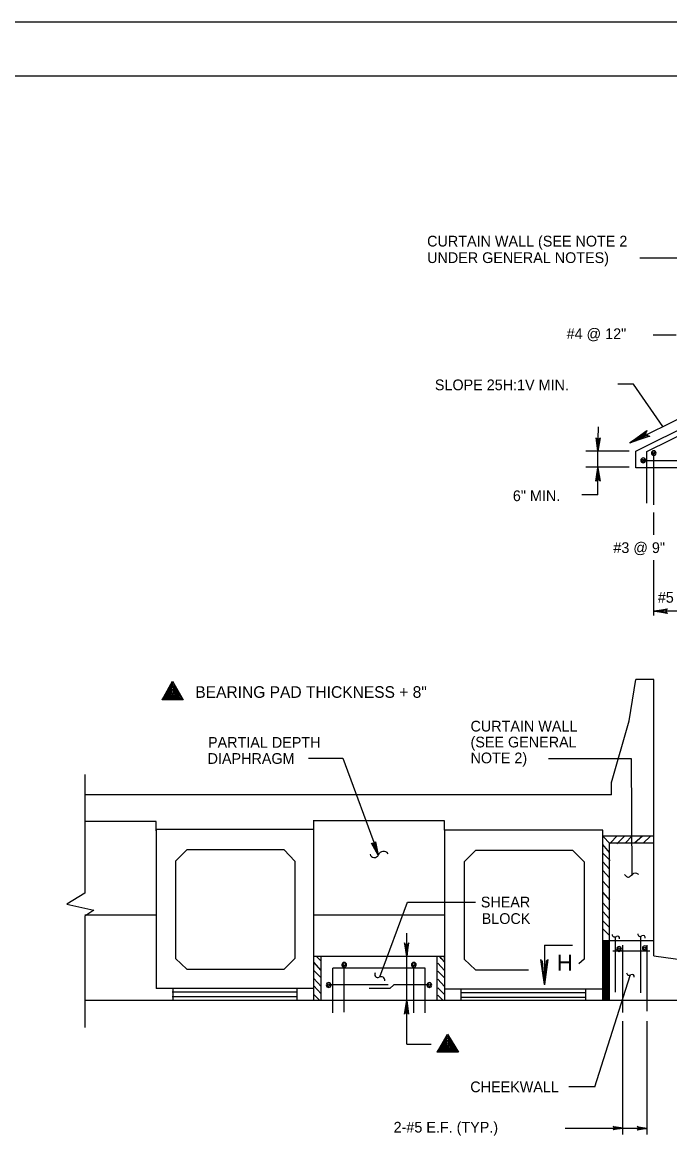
# Model space of a CAD drawing. Extents: x 638091 to 638946, y 298288 to 298882.
# Drawn here: x 638535 to 638715.9, y 298569.7 to 298881.5 of the extents above; entities that cross this region are included whole.
import ezdxf

# ---------------------------------------------------------------- set-up
doc = ezdxf.new("R2010")
doc.units = 0
doc.layers.add('2', color=7, linetype='Continuous')
doc.layers.add('PLT-BNDY', color=7, linetype='Continuous')

msp = doc.modelspace()

# ---------------------------------------------------------------- linework, layer by layer
at = {"layer": '2'}
for p, q in [((638130.58, 298866.5), (638916.58, 298866.5)), ((638707.59, 298815.66), (638719.77, 298815.66)), ((638717.8, 298794.07), (638711.37, 298794.07)), ((638705.85, 298780.38), (638701.42, 298780.38)), ((638714.07, 298768.52), (638705.85, 298780.38)), ((638704.85, 298763.94), (638721.09, 298772)), ((638695.91, 298761.63), (638696.1, 298768.38)), ((638706.51, 298761.63), (638722.75, 298769.7)), ((638709.54, 298761.48), (638723.83, 298768.57)), ((638704.66, 298761.63), (638692.53, 298761.63)), ((638695.91, 298756.95), (638695.91, 298761.63)), ((638706.51, 298756.95), (638706.51, 298761.63)), ((638708.54, 298759.05), (638728.54, 298759.05)), ((638708.54, 298758.38), (638708.54, 298758.73)), ((638709.54, 298747.04), (638709.54, 298761.48)), ((638711.5, 298746.64), (638711.5, 298761.08)), ((638711.5, 298760.41), (638711.5, 298760.77)), ((638704.66, 298757.13), (638692.53, 298757.13)), ((638695.91, 298749.38), (638695.91, 298756.95)), ((638872.72, 298756.95), (638706.51, 298756.95)), ((638695.91, 298749.38), (638691.41, 298749.38)), ((638711.5, 298738.24), (638711.5, 298744.51)), ((638711.5, 298715.67), (638711.5, 298731.15)), ((638813.89, 298716.87), (638711.5, 298716.87)), ((638704.6, 298686.2), (638706.47, 298697.82)), ((638711.53, 298697.82), (638706.47, 298697.82)), ((638711.53, 298653.95), (638711.53, 298697.82)), ((638699.72, 298668.95), (638704.6, 298686.2)), ((638614.96, 298675.78), (638624.6, 298675.78)), ((638624.6, 298675.78), (638634.56, 298648.73)), ((638682.1, 298675.7), (638705.16, 298675.7)), ((638705.16, 298675.7), (638705.35, 298643.07)), ((638552.53, 298671.2), (638552.53, 298638.01)), ((638699.72, 298665.57), (638699.72, 298669.14)), ((638699.72, 298665.57), (638552.53, 298665.57)), ((638572.41, 298658.07), (638552.53, 298658.07)), ((638572.41, 298655.45), (638572.41, 298658.07)), ((638572.41, 298655.82), (638572.41, 298611.39)), ((638616.47, 298655.82), (638572.41, 298655.82)), ((638616.47, 298655.82), (638616.47, 298658.45)), ((638653.03, 298658.26), (638616.47, 298658.26)), ((638616.47, 298608.01), (638616.47, 298655.82)), ((638653.03, 298655.64), (638653.03, 298658.26)), ((638653.03, 298655.64), (638653.03, 298608.01)), ((638697.28, 298655.64), (638653.03, 298655.64)), ((638697.28, 298608.01), (638697.28, 298655.64)), ((638697.28, 298653.95), (638699.35, 298651.89)), ((638711.53, 298653.95), (638697.28, 298653.95)), ((638701.22, 298653.95), (638699.53, 298652.26)), ((638703.28, 298653.95), (638701.22, 298651.89)), ((638705.53, 298654.14), (638703.47, 298652.07)), ((638708.35, 298653.95), (638706.1, 298652.07)), ((638710.6, 298653.95), (638708.53, 298652.07)), ((638711.53, 298620.57), (638711.53, 298653.95)), ((638577.85, 298647.01), (638581.03, 298650.2)), ((638608.22, 298650.2), (638581.03, 298650.2)), ((638608.22, 298650.2), (638611.22, 298647.01)), ((638658.47, 298646.82), (638661.66, 298650.01)), ((638688.85, 298650.01), (638661.66, 298650.01)), ((638688.85, 298650.01), (638692.03, 298646.82)), ((638699.16, 298649.45), (638697.28, 298651.7)), ((638699.16, 298608.01), (638699.16, 298652.07)), ((638711.53, 298652.07), (638699.16, 298652.07)), ((638577.85, 298647.01), (638577.85, 298619.82)), ((638611.22, 298647.01), (638611.22, 298619.82)), ((638658.47, 298646.82), (638658.47, 298619.64)), ((638692.03, 298646.82), (638692.03, 298619.64)), ((638697.28, 298649.26), (638699.35, 298647.2)), ((638699.16, 298644.76), (638697.28, 298646.82)), ((638699.16, 298642.32), (638697.28, 298644.39)), ((638699.16, 298639.32), (638697.28, 298641.39)), ((638697.28, 298638.2), (638699.16, 298636.14)), ((638634.96, 298614.65), (638642.72, 298635.57)), ((638642.72, 298635.57), (638661.66, 298635.57)), ((638699.16, 298633.32), (638697.28, 298635.39)), ((638572.41, 298631.89), (638552.53, 298631.89)), ((638552.53, 298631.64), (638552.53, 298600.51)), ((638653.03, 298631.89), (638616.47, 298631.89)), ((638699.16, 298630.89), (638697.28, 298632.95)), ((638699.16, 298628.45), (638697.28, 298630.32)), ((638699.16, 298626.2), (638697.28, 298628.07)), ((638642.46, 298595.82), (638642.46, 298626.86)), ((638699.16, 298624.7), (638697.28, 298624.7)), ((638697.47, 298608.01), (638697.47, 298624.7)), ((638697.85, 298608.01), (638697.85, 298624.7)), ((638698.22, 298608.01), (638698.22, 298624.7)), ((638698.6, 298608.01), (638698.6, 298624.7)), ((638698.97, 298608.01), (638698.97, 298624.7)), ((638711.53, 298624.7), (638699.16, 298624.7)), ((638700.83, 298610.36), (638700.83, 298625.73)), ((638707.89, 298610.17), (638707.89, 298625.92)), ((638680.92, 298623.53), (638680.92, 298612.4)), ((638680.92, 298623.53), (638688.75, 298623.53)), ((638710.4, 298621.8), (638700.09, 298621.8)), ((638701.79, 298621.77), (638701.79, 298622.12)), ((638702.87, 298604.73), (638702.87, 298623.51)), ((638708.97, 298621.99), (638708.97, 298622.35)), ((638709.61, 298605.11), (638709.61, 298623.51)), ((638581.03, 298616.82), (638577.85, 298619.82)), ((638611.22, 298619.82), (638608.22, 298616.82)), ((638653.03, 298620.39), (638616.47, 298620.39)), ((638618.53, 298616.45), (638616.47, 298618.72)), ((638618.53, 298619.07), (638617.22, 298620.39)), ((638618.53, 298608.01), (638618.53, 298620.39)), ((638650.97, 298608.01), (638650.97, 298620.39)), ((638653.03, 298616.45), (638651.16, 298618.51)), ((638653.03, 298618.89), (638651.72, 298620.39)), ((638652.1, 298619.82), (638651.72, 298620.39)), ((638653.03, 298619.82), (638653.03, 298620.39)), ((638661.66, 298616.64), (638658.47, 298619.64)), ((638692.03, 298619.64), (638690.57, 298618.26)), ((638711.53, 298620.57), (638754.44, 298614.58)), ((638581.03, 298616.82), (638608.22, 298616.82)), ((638618.53, 298614.39), (638616.47, 298616.45)), ((638621.8, 298604.64), (638621.8, 298617.09)), ((638647.62, 298617.09), (638621.8, 298617.09)), ((638624.95, 298604.82), (638624.95, 298617.19)), ((638624.98, 298617.37), (638624.98, 298617.73)), ((638644.43, 298617.36), (638644.43, 298617.72)), ((638644.47, 298604.64), (638644.47, 298617.01)), ((638647.62, 298604.64), (638647.62, 298617.09)), ((638653.03, 298614.39), (638651.16, 298616.26)), ((638661.66, 298616.64), (638676.52, 298616.64)), ((638695.05, 298583.87), (638704.9, 298615.08)), ((638618.53, 298611.95), (638616.47, 298614.22)), ((638618.53, 298609.87), (638616.47, 298612.16)), ((638620.64, 298611.7), (638620.64, 298612.06)), ((638637.23, 298612.47), (638620.67, 298612.47)), ((638637.78, 298611.41), (638638.85, 298612.47)), ((638648.35, 298612.47), (638638.85, 298612.47)), ((638648.79, 298611.71), (638648.79, 298612.07)), ((638653.03, 298611.95), (638651.16, 298614.01)), ((638616.47, 298611.39), (638572.41, 298611.39)), ((638576.91, 298610.45), (638611.78, 298610.45)), ((638576.91, 298609.14), (638611.78, 298609.14)), ((638577.1, 298611.2), (638577.1, 298608.01)), ((638611.78, 298611.39), (638611.78, 298608.01)), ((638618.16, 298608.01), (638616.47, 298609.7)), ((638637.78, 298611.41), (638631.92, 298611.41)), ((638653.03, 298609.7), (638651.16, 298611.57)), ((638652.66, 298608.01), (638651.16, 298609.51)), ((638697.28, 298611.2), (638653.03, 298611.2)), ((638657.53, 298608.95), (638692.41, 298608.95)), ((638657.6, 298611.21), (638657.6, 298608.02)), ((638657.72, 298610.26), (638692.41, 298610.26)), ((638692.41, 298611.21), (638692.41, 298608.02)), ((638754.44, 298608.01), (638552.53, 298608.01)), ((638702.87, 298570.62), (638702.87, 298602.23)), ((638709.61, 298570.62), (638709.61, 298602.23)), ((638642.46, 298595.82), (638649.3, 298595.82)), ((638695.05, 298583.87), (638687.76, 298583.87)), ((638709.61, 298572.31), (638686.74, 298572.31))]:
    msp.add_line(p, q, dxfattribs=at)
for points in [[(638696.41, 298765.13), (638696.16, 298765.01), (638695.91, 298761.63), (638696.41, 298765.13), (638696.53, 298765.38), (638695.91, 298761.63), (638695.78, 298765.01), (638695.53, 298765.13), (638695.91, 298761.63), (638695.41, 298765.38), (638695.53, 298765.13)], [(638710.06, 298765.82), (638709.71, 298766.06), (638704.85, 298763.94), (638710.06, 298765.82), (638710.43, 298765.77), (638704.85, 298763.94), (638709.42, 298766.68), (638709.48, 298767.05), (638704.85, 298763.94), (638709.53, 298767.42), (638709.48, 298767.05)], [(638695.53, 298753.45), (638695.78, 298753.57), (638695.91, 298756.95), (638695.53, 298753.45), (638695.28, 298753.2), (638695.91, 298756.95), (638696.16, 298753.57), (638696.41, 298753.45), (638695.91, 298756.95), (638696.53, 298753.2), (638696.41, 298753.45)], [(638715.13, 298716.5), (638715, 298716.75), (638711.5, 298716.87), (638715.13, 298716.5), (638715.25, 298716.25), (638711.5, 298716.87), (638715, 298717.12), (638715.13, 298717.37), (638711.5, 298716.87), (638715.25, 298717.5), (638715.13, 298717.37)], [(638574.08, 298692.13), (638576.96, 298697.35), (638580.02, 298692.13), (638574.08, 298692.13), (638577.14, 298696.99), (638579.66, 298692.31), (638574.26, 298692.31), (638577.14, 298696.45), (638579.48, 298692.49), (638574.62, 298692.49), (638577.14, 298696.09), (638578.94, 298692.67), (638575.16, 298692.67), (638576.96, 298695.73), (638578.58, 298692.85), (638575.52, 298692.85), (638576.96, 298695.19), (638578.22, 298693.03), (638575.88, 298693.03), (638576.96, 298694.83), (638577.86, 298693.21), (638576.24, 298693.21), (638576.96, 298694.29), (638577.32, 298693.57), (638576.78, 298693.57), (638576.96, 298693.75)], [(638633.6, 298652.32), (638633.47, 298652.07), (638634.47, 298648.7), (638633.6, 298652.32), (638633.72, 298652.45), (638634.47, 298648.7), (638633.09, 298651.95), (638632.84, 298651.95), (638634.47, 298648.7), (638632.59, 298652.07), (638632.84, 298651.95)], [(638552.53, 298638.01), (638547.47, 298635.01), (638554.97, 298633.32), (638552.53, 298631.64)], [(638641.96, 298623.89), (638642.21, 298623.76), (638642.46, 298620.39), (638641.96, 298623.89), (638641.84, 298624.14), (638642.46, 298620.39), (638642.59, 298623.76), (638642.84, 298623.89), (638642.46, 298620.39), (638643.09, 298624.14), (638642.84, 298623.89)], [(638681.92, 298619.28), (638681.42, 298619.03), (638680.92, 298612.53), (638681.92, 298619.28), (638681.92, 298619.53), (638680.92, 298612.53), (638680.42, 298619.03), (638679.92, 298619.03), (638680.92, 298612.53), (638679.92, 298619.53), (638679.92, 298619.03)], [(638641.96, 298604.51), (638642.21, 298604.64), (638642.46, 298608.01), (638641.96, 298604.51), (638641.84, 298604.26), (638642.46, 298608.01), (638642.59, 298604.64), (638642.84, 298604.51), (638642.46, 298608.01), (638642.96, 298604.26), (638642.84, 298604.51)], [(638651, 298593.63), (638653.88, 298598.67), (638656.94, 298593.63), (638651, 298593.63), (638653.88, 298598.31), (638656.58, 298593.81), (638651.18, 298593.81), (638653.88, 298597.95), (638656.4, 298593.99), (638651.54, 298593.99), (638653.88, 298597.59), (638655.86, 298594.17), (638651.9, 298594.17), (638653.88, 298597.05), (638655.5, 298594.35), (638652.26, 298594.35), (638653.88, 298596.69), (638655.14, 298594.53), (638652.8, 298594.53), (638653.88, 298596.15), (638654.78, 298594.71), (638653.16, 298594.71), (638653.88, 298595.61), (638654.24, 298595.07), (638653.7, 298595.07), (638653.88, 298595.25)], [(638700.3, 298572.72), (638700.43, 298572.47), (638702.93, 298572.35), (638700.3, 298572.72), (638700.18, 298572.85), (638702.93, 298572.35), (638700.43, 298572.22), (638700.3, 298572.1), (638702.93, 298572.35), (638700.18, 298571.85), (638700.3, 298572.1)], [(638707.11, 298572.68), (638707.11, 298572.43), (638709.61, 298572.31), (638707.11, 298572.68), (638706.86, 298572.81), (638709.61, 298572.31), (638707.11, 298572.18), (638707.11, 298572.06), (638709.61, 298572.31), (638706.86, 298571.81), (638707.11, 298572.06)]]:
    msp.add_lwpolyline(points, dxfattribs=at)
for centre in [(638708.54, 298759.05), (638711.5, 298761.08), (638701.79, 298622.44), (638708.98, 298622.66), (638624.99, 298618.04), (638644.43, 298618.04), (638620.64, 298612.37), (638648.79, 298612.38)]:
    msp.add_circle(centre, 0.314, dxfattribs=at)
for centre, radius, start, end in [((638711.5, 298761.08), 0.671, 269.6129, 268.6063), ((638708.54, 298759.05), 0.671, 271.3937, 270.3871), ((638636, 298648.21), 1.53, 35.4213, 160.213), ((638633.43, 298649.27), 1.25, 193.8117, 334.5116), ((638700.6, 298626.55), 0.738, 183.3846, 308.1762), ((638701.38, 298625.46), 0.601, 341.7749, 122.4748), ((638707.74, 298626.71), 0.738, 183.3846, 308.1762), ((638708.52, 298625.62), 0.601, 341.7749, 122.4748), ((638701.79, 298622.44), 0.671, 269.6129, 268.6063), ((638708.98, 298622.66), 0.671, 269.6129, 268.6063), ((638624.99, 298618.04), 0.671, 269.6129, 268.6063), ((638644.43, 298618.04), 0.671, 269.6129, 268.6063), ((638634.39, 298615.39), 0.89, 153.2611, 293.961), ((638704.65, 298615.83), 0.738, 183.3846, 308.1762), ((638705.42, 298614.75), 0.601, 341.7749, 122.4748), ((638620.64, 298612.37), 0.671, 269.6129, 268.6063), ((638635.29, 298613.62), 1.09, 354.8707, 119.6623), ((638648.79, 298612.38), 0.671, 269.6129, 268.6063)]:
    msp.add_arc(centre, radius, start, end, dxfattribs=at)
msp.add_spline([(638703.28, 298643.26), (638703.66, 298642.89), (638704.41, 298642.51), (638704.97, 298642.89), (638705.53, 298643.26), (638705.91, 298643.64), (638706.66, 298643.64), (638707.03, 298643.45), (638707.22, 298643.26)], degree=3, dxfattribs=at)
at = {"layer": 'PLT-BNDY'}
msp.add_lwpolyline([(638090.58, 298287.5), (638931.58, 298287.5), (638931.58, 298881.5), (638090.58, 298881.5)], close=True, dxfattribs=at)

# ---------------------------------------------------------------- texts
at = {"layer": '2'}
for s, height, p in [('CURTAIN WALL (SEE NOTE 2', 3, (638648.16, 298818.83)), ('UNDER GENERAL NOTES)', 3, (638648.16, 298814.21)), ('#4 @ 12"', 3, (638687.15, 298792.93)), ('SLOPE 25H:1V MIN.', 2.9999, (638650.33, 298778.65)), ('6" MIN.', 3, (638672.12, 298747.64)), ('#3 @ 9"', 3, (638700.21, 298733.14)), ('#5 @ 12"', 3, (638712.63, 298719.25)), ('BEARING PAD THICKNESS + 8"', 3.2501, (638583.38, 298692.66)), ('CURTAIN WALL', 3.0001, (638660.29, 298683.24)), ('PARTIAL DEPTH', 3.0001, (638586.93, 298678.7)), ('(SEE GENERAL', 3.0001, (638660.29, 298678.8)), ('NOTE 2)', 3, (638660.29, 298674.36)), ('DIAPHRAGM', 3, (638586.81, 298674.2)), ('SHEAR', 3, (638663.16, 298634.07)), ('BLOCK', 3, (638663.41, 298629.45)), ('H', 4.5, (638684.47, 298616.4)), ('CHEEKWALL', 3, (638660.22, 298582.41)), ('2-#5 E.F. (TYP.)', 3, (638638.79, 298571.13))]:
    msp.add_text(s, height=height, dxfattribs=at).set_placement(p)

doc.saveas('drawing.dxf')
